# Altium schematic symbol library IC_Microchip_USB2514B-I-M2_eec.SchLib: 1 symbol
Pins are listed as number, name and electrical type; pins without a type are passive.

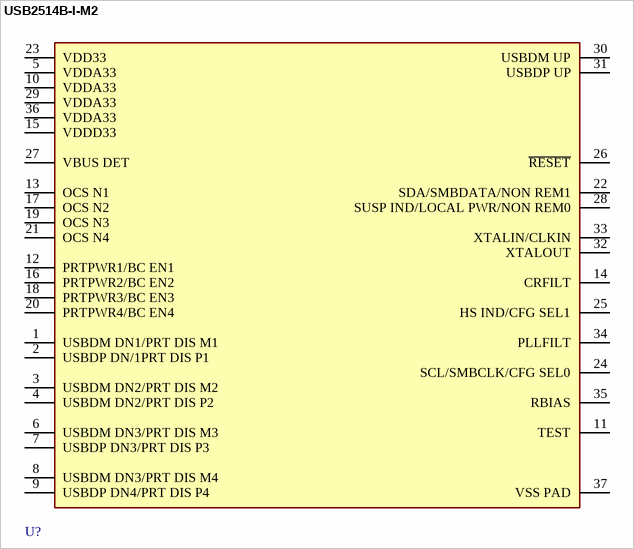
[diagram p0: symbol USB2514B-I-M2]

## USB2514B-I-M2
designator U?  (value not drawn)
pins: 1 USBDM DN1/PRT DIS M1, 2 USBDP DN/1PRT DIS P1, 3 USBDM DN2/PRT DIS M2, 4 USBDM DN2/PRT DIS P2, 5 VDDA33, 6 USBDM DN3/PRT DIS M3, 7 USBDP DN3/PRT DIS P3, 8 USBDM DN3/PRT DIS M4, 9 USBDP DN4/PRT DIS P4, 10 VDDA33, 11 TEST, 12 PRTPWR1/BC EN1, 13 OCS N1, 14 CRFILT, 15 VDDD33, 16 PRTPWR2/BC EN2, 17 OCS N2, 18 PRTPWR3/BC EN3, 19 OCS N3, 20 PRTPWR4/BC EN4, 21 OCS N4, 22 SDA/SMBDATA/NON REM1, 23 VDD33, 24 SCL/SMBCLK/CFG SEL0, 25 HS IND/CFG SEL1, 26 ~{RESET}, 27 VBUS DET, 28 SUSP IND/LOCAL PWR/NON REM0, 29 VDDA33, 30 USBDM UP, 31 USBDP UP, 32 XTALOUT, 33 XTALIN/CLKIN, 34 PLLFILT, 35 RBIAS, 36 VDDA33, 37 VSS PAD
